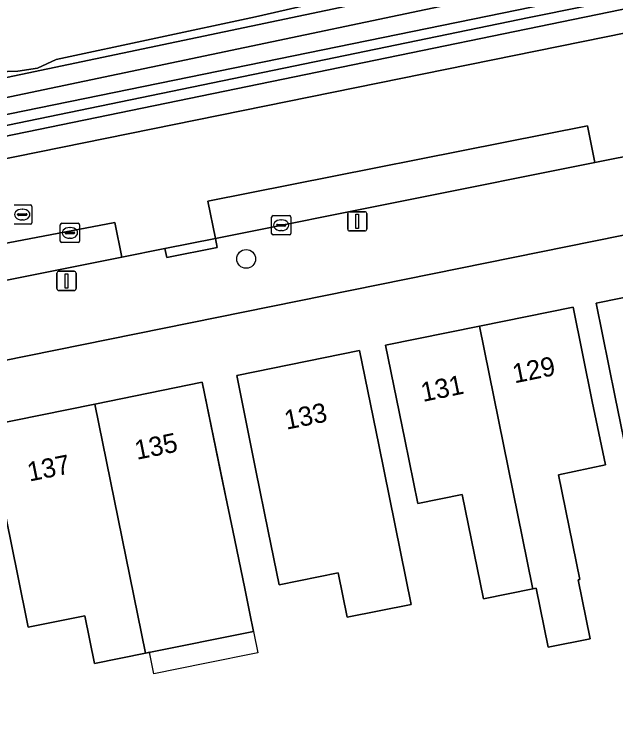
# Model space of a CAD drawing. Extents: x 162989 to 165008, y 383432 to 384338.
# Drawn here: x 163532.42 to 163563.71, y 384033.07 to 384069.7 of the extents above; entities that cross this region are included whole.
import ezdxf

# ---------------------------------------------------------------- set-up
doc = ezdxf.new("R2010")
doc.units = 0
for name, color, linetype in [('IMGEO_Boom', 7, 'Continuous'), ('IMGEO_Brandkraan', 7, 'Continuous'), ('IMGEO_Erf', 7, 'Continuous'), ('IMGEO_Grasland_overig', 7, 'Continuous'), ('IMGEO_Greppel_droge_sloot', 7, 'Continuous'), ('IMGEO_Groenvoorziening', 7, 'Continuous'), ('IMGEO_Haag', 7, 'Continuous'), ('IMGEO_Hek', 7, 'Continuous'), ('IMGEO_Kolk', 7, 'Continuous'), ('IMGEO_Lichtmast', 7, 'Continuous'), ('IMGEO_Pand', 7, 'Continuous'), ('IMGEO_Pand_nummerreeks', 7, 'Continuous'), ('IMGEO_Pand_vergunning_verleend', 7, 'Continuous'), ('IMGEO_Parkeervlak_gesloten', 7, 'Continuous'), ('IMGEO_Rijbaan_lokaal_gesloten', 7, 'Continuous'), ('IMGEO_Rioolput', 7, 'Continuous'), ('IMGEO_Spoorbaan_halfverhard', 7, 'Continuous'), ('IMGEO_Voetpad_open', 7, 'Continuous')]:
    doc.layers.add(name, color=color, linetype=linetype)

msp = doc.modelspace()

# ---------------------------------------------------------------- linework, layer by layer
at = {"layer": 'IMGEO_Boom'}
msp.add_circle((163544.485, 384056.956), 0.489, dxfattribs=at)
at = {"layer": 'IMGEO_Brandkraan'}
for p, q in [((163534.895, 384058.81), (163535.747, 384058.81)), ((163534.82, 384057.884), (163534.82, 384058.736)), ((163535.308, 384058.59), (163535.333, 384058.59)), ((163535.821, 384058.736), (163535.821, 384057.884)), ((163535.079, 384058.304), (163535.079, 384058.316)), ((163535.517, 384058.267), (163535.119, 384058.267)), ((163535.122, 384058.353), (163535.52, 384058.353)), ((163535.563, 384058.316), (163535.563, 384058.304)), ((163535.747, 384057.81), (163534.895, 384057.81)), ((163535.331, 384058.03), (163535.306, 384058.03))]:
    msp.add_line(p, q, dxfattribs=at)
for points in [[(163534.895, 384058.81), (163535.747, 384058.81)], [(163534.82, 384057.884), (163534.82, 384058.736)], [(163535.821, 384058.736), (163535.821, 384057.884)], [(163535.747, 384057.81), (163534.895, 384057.81)]]:
    msp.add_lwpolyline(points, dxfattribs=at)
for centre, radius, start, end in [((163534.897, 384058.734), 0.0765, 91.552, 178.448), ((163534.897, 384058.734), 0.0765, 91.552, 178.448), ((163535.745, 384058.734), 0.0765, 1.552, 88.448), ((163535.745, 384058.734), 0.0765, 1.552, 88.448), ((163535.119, 384058.313), 0.0403, 85.8775, 175.7526), ((163535.116, 384058.303), 0.0366, 178.938, 274.7102), ((163535.52, 384058.31), 0.043, 264.8664, 352.4533), ((163535.524, 384058.315), 0.0386, 1.7309, 96.639), ((163534.897, 384057.886), 0.0765, 181.552, 268.448), ((163534.897, 384057.886), 0.0765, 181.552, 268.448), ((163535.745, 384057.886), 0.0765, 271.552, 358.448), ((163535.745, 384057.886), 0.0765, 271.552, 358.448)]:
    msp.add_arc(centre, radius, start, end, dxfattribs=at)
for centre, major_axis, ratio, start_param, end_param in [((163535.307, 384058.31), (-0.387, 0.002), 0.722429, 4.712389, 7.853982), ((163535.332, 384058.31), (-0.39, 0.002), 0.717154, 1.570796, 4.712389)]:
    msp.add_ellipse(centre, major_axis=major_axis, ratio=ratio, start_param=start_param, end_param=end_param, dxfattribs=at)
at = {"layer": 'IMGEO_Erf'}
msp.add_lwpolyline([(163571.675, 384023.898), (163570.606, 384023.676), (163567.521, 384023.037), (163565.815, 384029.374), (163562.598, 384028.708), (163561.933, 384031.921), (163566.989, 384032.968), (163567.654, 384029.755), (163568.81, 384029.994), (163569.078, 384030.05), (163568.17, 384033.338), (163567.049, 384033.106), (163565.959, 384038.486), (163565.183, 384042.315), (163564.24, 384046.969), (163563.675, 384049.758), (163562.681, 384054.658), (163568.762, 384055.891), (163570.284, 384048.388), (163575.932, 384049.533), (163573.788, 384060.144), (163530.361, 384051.352), (163527.117, 384050.695), (163506.394, 384046.506)], dxfattribs=at)
for points in [[(163551.737, 384052.465), (163556.612, 384053.454), (163561.491, 384054.443), (163562.484, 384049.543), (163563.173, 384046.232), (163560.729, 384045.715), (163561.832, 384040.273), (163561.757, 384040.258), (163562.379, 384037.191), (163560.191, 384036.748), (163559.57, 384039.815), (163559.398, 384039.78), (163556.829, 384039.259), (163555.727, 384044.696), (163553.408, 384044.226), (163552.731, 384047.565)], [(163543.992, 384050.887), (163550.385, 384052.184), (163551.379, 384047.284), (163553.063, 384038.979), (163549.738, 384038.305), (163549.267, 384040.626), (163546.198, 384040.003), (163545.635, 384042.782), (163544.994, 384045.945)], [(163532.023, 384043.37), (163531.029, 384048.27), (163536.618, 384049.403), (163542.203, 384050.536), (163543.197, 384045.637), (163543.798, 384042.817), (163544.408, 384039.811), (163544.673, 384038.506), (163544.864, 384037.566), (163539.256, 384036.444), (163536.597, 384035.904), (163536.094, 384038.386), (163533.156, 384037.786), (163532.595, 384040.551)]]:
    msp.add_lwpolyline(points, close=True, dxfattribs=at)
at = {"layer": 'IMGEO_Grasland_overig'}
msp.add_lwpolyline([(163567.891, 384071.31), (163567.147, 384072.016), (163567.019, 384073.036), (163567.705, 384073.624), (163568.981, 384073.967), (163576.539, 384075.585), (163576.38, 384076.349), (163564.027, 384073.934), (163544.976, 384069.548), (163534.604, 384067.329), (163533.632, 384066.876), (163532.615, 384066.725), (163530.964, 384066.68), (163496.927, 384059.282), (163496.482, 384058.939), (163551.444, 384070.499), (163563.608, 384072.965), (163564.314, 384072.884), (163564.557, 384072.489), (163564.885, 384070.689)], close=True, dxfattribs=at)
at = {"layer": 'IMGEO_Greppel_droge_sloot'}
for points in [[(163564.885, 384070.689), (163564.557, 384072.489), (163564.314, 384072.884), (163563.608, 384072.965), (163551.444, 384070.499), (163496.482, 384058.939), (163481.272, 384055.806), (163480.976, 384055.531), (163480.854, 384055.133), (163480.891, 384054.4), (163481.106, 384053.827), (163481.381, 384053.662), (163481.625, 384053.535), (163494.89, 384056.228), (163559.208, 384069.516)], [(163562.988, 384071.656), (163555.555, 384070.298), (163529.787, 384064.894), (163481.54, 384055.015), (163481.436, 384054.813), (163481.452, 384054.547), (163481.731, 384054.178), (163563.229, 384070.88)], [(163555.555, 384070.298), (163562.988, 384071.656), (163563.229, 384070.88), (163481.731, 384054.178), (163481.452, 384054.547), (163481.436, 384054.813), (163481.54, 384055.015), (163529.787, 384064.894)]]:
    msp.add_lwpolyline(points, close=True, dxfattribs=at)
at = {"layer": 'IMGEO_Groenvoorziening'}
for points in [[(163721.236, 384103.128), (163651.615, 384088.607), (163609.784, 384079.965), (163577.034, 384073.199), (163567.891, 384071.31), (163564.885, 384070.689), (163559.208, 384069.516), (163494.89, 384056.228), (163481.625, 384053.535), (163459.651, 384049.074), (163442.263, 384045.543), (163422.031, 384041.436), (163419.561, 384040.874), (163408.564, 384037.598), (163408.734, 384037.023), (163409.522, 384037.258), (163419.713, 384040.294), (163422.158, 384040.849), (163459.771, 384048.486), (163651.736, 384088.019), (163830.895, 384125.387)], [(163830.895, 384125.387), (163651.736, 384088.019), (163459.771, 384048.486), (163422.158, 384040.849), (163419.713, 384040.294), (163409.522, 384037.258), (163408.734, 384037.023), (163409.808, 384036.105), (163410.773, 384036.455), (163412.582, 384037.103), (163414.405, 384037.712), (163416.239, 384038.284), (163418.085, 384038.817), (163419.942, 384039.312), (163421.809, 384039.768), (163423.331, 384040.11), (163470.865, 384049.76), (163474.78, 384050.554), (163569.015, 384069.685), (163584.838, 384072.976), (163644.593, 384085.348), (163648.507, 384086.167), (163682.411, 384093.294), (163707.965, 384098.574)]]:
    msp.add_lwpolyline(points, dxfattribs=at)
at = {"layer": 'IMGEO_Haag'}
msp.add_lwpolyline([(163721.236, 384103.128), (163651.615, 384088.607), (163609.784, 384079.965), (163577.034, 384073.199), (163567.891, 384071.31), (163564.885, 384070.689), (163559.208, 384069.516), (163494.89, 384056.228), (163481.625, 384053.535), (163459.651, 384049.074), (163442.263, 384045.543), (163422.031, 384041.436), (163419.561, 384040.874), (163408.564, 384037.598), (163408.734, 384037.023), (163409.522, 384037.258), (163419.713, 384040.294), (163422.158, 384040.849), (163459.771, 384048.486), (163651.736, 384088.019), (163830.895, 384125.387)], dxfattribs=at)
at = {"layer": 'IMGEO_Hek'}
msp.add_lwpolyline([(163830.751, 384125.97), (163651.615, 384088.607), (163494.89, 384056.228), (163459.651, 384049.074)], dxfattribs=at)
at = {"layer": 'IMGEO_Kolk'}
for p, q in [((163545.881, 384059.21), (163546.733, 384059.21)), ((163545.806, 384058.284), (163545.806, 384059.136)), ((163546.294, 384058.99), (163546.319, 384058.99)), ((163546.807, 384059.136), (163546.807, 384058.284)), ((163546.065, 384058.704), (163546.065, 384058.716)), ((163546.503, 384058.667), (163546.105, 384058.667)), ((163546.108, 384058.753), (163546.506, 384058.753)), ((163546.317, 384058.43), (163546.292, 384058.43)), ((163546.549, 384058.716), (163546.549, 384058.704)), ((163546.733, 384058.21), (163545.881, 384058.21))]:
    msp.add_line(p, q, dxfattribs=at)
for points in [[(163545.881, 384059.21), (163546.733, 384059.21)], [(163545.806, 384058.284), (163545.806, 384059.136)], [(163546.807, 384059.136), (163546.807, 384058.284)], [(163546.733, 384058.21), (163545.881, 384058.21)]]:
    msp.add_lwpolyline(points, dxfattribs=at)
for centre, radius, start, end in [((163545.883, 384059.134), 0.0765, 91.552, 178.448), ((163545.883, 384059.134), 0.0765, 91.552, 178.448), ((163546.731, 384059.134), 0.0765, 1.552, 88.448), ((163546.731, 384059.134), 0.0765, 1.552, 88.448), ((163546.105, 384058.713), 0.0403, 85.8775, 175.7526), ((163546.102, 384058.703), 0.0366, 178.938, 274.7102), ((163546.506, 384058.71), 0.043, 264.8664, 352.4533), ((163546.51, 384058.715), 0.0386, 1.7309, 96.639), ((163545.883, 384058.286), 0.0765, 181.552, 268.448), ((163545.883, 384058.286), 0.0765, 181.552, 268.448), ((163546.731, 384058.286), 0.0765, 271.552, 358.448), ((163546.731, 384058.286), 0.0765, 271.552, 358.448)]:
    msp.add_arc(centre, radius, start, end, dxfattribs=at)
for centre, major_axis, ratio, start_param, end_param in [((163546.293, 384058.71), (-0.387, 0.002), 0.722429, 4.712389, 7.853982), ((163546.318, 384058.71), (-0.39, 0.002), 0.717154, 1.570796, 4.712389)]:
    msp.add_ellipse(centre, major_axis=major_axis, ratio=ratio, start_param=start_param, end_param=end_param, dxfattribs=at)
at = {"layer": 'IMGEO_Lichtmast'}
for p, q in [((163549.765, 384058.513), (163549.765, 384059.313)), ((163549.765, 384059.313), (163549.765, 384058.513)), ((163549.865, 384059.413), (163550.655, 384059.413)), ((163550.655, 384059.413), (163549.865, 384059.413)), ((163550.755, 384059.313), (163550.755, 384058.513)), ((163550.755, 384058.513), (163550.755, 384059.313)), ((163550.655, 384058.413), (163549.865, 384058.413)), ((163549.865, 384058.413), (163550.655, 384058.413)), ((163534.746, 384056.311), (163535.536, 384056.311)), ((163535.536, 384056.311), (163534.746, 384056.311)), ((163534.646, 384055.411), (163534.646, 384056.211)), ((163534.646, 384056.211), (163534.646, 384055.411)), ((163535.636, 384056.211), (163535.636, 384055.411)), ((163535.636, 384055.411), (163535.636, 384056.211)), ((163535.536, 384055.311), (163534.746, 384055.311)), ((163534.746, 384055.311), (163535.536, 384055.311))]:
    msp.add_line(p, q, dxfattribs=at)
for points in [[(163550.185, 384059.288), (163550.335, 384059.288), (163550.335, 384058.538), (163550.185, 384058.538), (163550.185, 384059.288)], [(163535.066, 384056.186), (163535.216, 384056.186), (163535.216, 384055.436), (163535.066, 384055.436), (163535.066, 384056.186)]]:
    msp.add_lwpolyline(points, dxfattribs=at)
for centre, start, end in [((163549.865, 384059.313), 90, 180), ((163549.865, 384059.313), 90, 180), ((163550.655, 384059.313), 0, 90), ((163550.655, 384059.313), 360, 90), ((163549.865, 384058.513), 180, 270), ((163549.865, 384058.513), 180, 270), ((163550.655, 384058.513), 270, 0), ((163550.655, 384058.513), 270, 0), ((163534.746, 384056.211), 90, 180), ((163534.746, 384056.211), 90, 180), ((163535.536, 384056.211), 0, 90), ((163535.536, 384056.211), 360, 90), ((163534.746, 384055.411), 180, 270), ((163534.746, 384055.411), 180, 270), ((163535.536, 384055.411), 270, 0), ((163535.536, 384055.411), 270, 0)]:
    msp.add_arc(centre, 0.1, start, end, dxfattribs=at)
at = {"layer": 'IMGEO_Pand'}
for points in [[(163575.932, 384049.533), (163570.284, 384048.388), (163568.762, 384055.891), (163562.681, 384054.658), (163563.675, 384049.758), (163564.24, 384046.969), (163565.183, 384042.315), (163565.959, 384038.486), (163566.706, 384038.641), (163569.122, 384039.142), (163568.3, 384042.93), (163570.04, 384043.274), (163574.961, 384044.247), (163574.692, 384045.575), (163576.651, 384045.972)], [(163562.484, 384049.543), (163561.491, 384054.443), (163556.612, 384053.454), (163559.353, 384039.947), (163559.398, 384039.78), (163559.57, 384039.815), (163560.191, 384036.748), (163562.379, 384037.191), (163561.757, 384040.258), (163561.832, 384040.273), (163560.729, 384045.715), (163563.173, 384046.232)], [(163559.398, 384039.78), (163559.353, 384039.947), (163556.612, 384053.454), (163551.737, 384052.465), (163552.731, 384047.565), (163553.408, 384044.226), (163555.727, 384044.696), (163556.829, 384039.259)], [(163551.379, 384047.284), (163550.385, 384052.184), (163543.992, 384050.887), (163544.994, 384045.945), (163545.635, 384042.782), (163546.198, 384040.003), (163549.267, 384040.626), (163549.738, 384038.305), (163553.063, 384038.979)], [(163543.197, 384045.637), (163542.203, 384050.536), (163536.618, 384049.403), (163539.256, 384036.444), (163544.864, 384037.566), (163544.673, 384038.506), (163544.408, 384039.811), (163543.798, 384042.817)], [(163536.618, 384049.403), (163531.029, 384048.27), (163532.023, 384043.37), (163532.595, 384040.551), (163533.156, 384037.786), (163536.094, 384038.386), (163536.597, 384035.904), (163539.256, 384036.444)]]:
    msp.add_lwpolyline(points, close=True, dxfattribs=at)
at = {"layer": 'IMGEO_Pand_vergunning_verleend'}
msp.add_lwpolyline([(163536.618, 384049.403), (163542.203, 384050.536), (163544.673, 384038.506), (163545.089, 384036.452), (163542.336, 384035.894), (163539.682, 384035.356), (163539.454, 384036.484), (163539.256, 384036.444)], close=True, dxfattribs=at)
at = {"layer": 'IMGEO_Parkeervlak_gesloten'}
for points in [[(163562.613, 384061.968), (163562.23, 384063.883), (163542.496, 384059.955), (163542.885, 384058.015)], [(163531.335, 384055.717), (163538.013, 384057.046), (163537.654, 384058.848), (163530.991, 384057.584)]]:
    msp.add_lwpolyline(points, close=True, dxfattribs=at)
at = {"layer": 'IMGEO_Rijbaan_lokaal_gesloten'}
msp.add_lwpolyline([(163562.613, 384061.968), (163570.204, 384063.489), (163569.015, 384069.685), (163474.78, 384050.554), (163475.982, 384044.399), (163481.25, 384045.474), (163485.275, 384046.295), (163500, 384049.301), (163501.629, 384049.627), (163505.545, 384050.443), (163511.524, 384051.675), (163511.116, 384053.482), (163524.323, 384056.16), (163524.689, 384054.387), (163525.413, 384054.536), (163530.123, 384055.476), (163531.335, 384055.717), (163530.991, 384057.584), (163537.654, 384058.848), (163538.013, 384057.046), (163540.262, 384057.493), (163542.885, 384058.015), (163542.496, 384059.955), (163562.23, 384063.883)], close=True, dxfattribs=at)
at = {"layer": 'IMGEO_Rioolput'}
for p, q in [((163532.416, 384059.764), (163533.268, 384059.764)), ((163532.829, 384059.544), (163532.854, 384059.544)), ((163533.342, 384059.69), (163533.342, 384058.838)), ((163532.6, 384059.258), (163532.6, 384059.27)), ((163533.038, 384059.221), (163532.64, 384059.221)), ((163532.643, 384059.307), (163533.041, 384059.307)), ((163533.084, 384059.27), (163533.084, 384059.258)), ((163532.852, 384058.984), (163532.827, 384058.984)), ((163533.268, 384058.764), (163532.416, 384058.764))]:
    msp.add_line(p, q, dxfattribs=at)
for points in [[(163532.416, 384059.764), (163533.268, 384059.764)], [(163533.342, 384059.69), (163533.342, 384058.838)], [(163533.268, 384058.764), (163532.416, 384058.764)]]:
    msp.add_lwpolyline(points, dxfattribs=at)
for centre, radius, start, end in [((163533.266, 384059.688), 0.0765, 1.552, 88.448), ((163533.266, 384059.688), 0.0765, 1.552, 88.448), ((163532.64, 384059.267), 0.0403, 85.8775, 175.7526), ((163532.637, 384059.257), 0.0366, 178.938, 274.7102), ((163533.041, 384059.264), 0.043, 264.8664, 352.4533), ((163533.045, 384059.269), 0.0386, 1.7309, 96.639), ((163533.266, 384058.84), 0.0765, 271.552, 358.448), ((163533.266, 384058.84), 0.0765, 271.552, 358.448)]:
    msp.add_arc(centre, radius, start, end, dxfattribs=at)
for centre, major_axis, ratio, start_param, end_param in [((163532.828, 384059.264), (-0.387, 0.002), 0.722429, 4.712389, 7.853982), ((163532.853, 384059.264), (-0.39, 0.002), 0.717154, 1.570796, 4.712389)]:
    msp.add_ellipse(centre, major_axis=major_axis, ratio=ratio, start_param=start_param, end_param=end_param, dxfattribs=at)
at = {"layer": 'IMGEO_Spoorbaan_halfverhard'}
msp.add_lwpolyline([(163496.927, 384059.282), (163530.964, 384066.68), (163532.615, 384066.725), (163533.632, 384066.876), (163534.604, 384067.329), (163544.976, 384069.548), (163564.027, 384073.934), (163576.38, 384076.349), (163574.156, 384087.056), (163570.605, 384086.317), (163570.301, 384086.046), (163559.311, 384083.67), (163533.28, 384078.494), (163532.988, 384078.486), (163529.295, 384077.717), (163528.462, 384077.141), (163512.279, 384073.997), (163500.004, 384071.187)], dxfattribs=at)
at = {"layer": 'IMGEO_Voetpad_open'}
msp.add_lwpolyline([(163571.591, 384063.591), (163570.204, 384063.489), (163562.613, 384061.968), (163542.885, 384058.015), (163542.979, 384057.551), (163540.354, 384057.037), (163540.262, 384057.493), (163538.013, 384057.046), (163531.335, 384055.717), (163530.123, 384055.476), (163530.361, 384051.352), (163573.788, 384060.144)], dxfattribs=at)
msp.add_lwpolyline([(163542.885, 384058.015), (163540.262, 384057.493), (163540.354, 384057.037), (163542.979, 384057.551)], close=True, dxfattribs=at)

# ---------------------------------------------------------------- texts
at = {"layer": 'IMGEO_Pand_nummerreeks'}
for s, rotation, p in [('129', 11.4649, (163558.443, 384050.478)), ('131', 11.4635, (163553.678, 384049.512)), ('133', 11.4684, (163546.579, 384048.065)), ('135', 11.4649, (163538.8, 384046.499)), ('137', 11.4649, (163533.213, 384045.366))]:
    msp.add_text(s, height=1, rotation=rotation, dxfattribs=at).set_placement(p)

doc.saveas('drawing.dxf')
